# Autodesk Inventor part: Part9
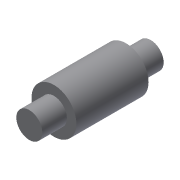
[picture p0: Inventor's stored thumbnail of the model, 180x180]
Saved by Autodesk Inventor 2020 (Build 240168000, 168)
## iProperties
Created: 2002-01
Part Number: Part9
Document SubType Name: Modeling
Designer: ***
Density: 1 g/cm^3
Material: Generic
Appearance: Default
Control State: 0
Master: False
Checked Out: False
Shininess: 77.0
Length Units: 11269
Angle Units: 11279
Time Units: 11290
Mass Units: 11283
Length Display Precision: 3
Angle Display Precision: 2
Density: 0.0
Volumn: 0.0
Area: 0.0
PropertySet Name: Model Information
Author: ***
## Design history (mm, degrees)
sketch "Sketch1"
  geometry: L1 (0.279, 23.245)-(5.19, 23.245); L2 (5.19, 23.245)-(5.19, 13.947); L3 (5.19, 13.947)-(8.761, 13.947); L4 (8.761, 13.947)-(8.761, -13.295); L5 (8.761, -13.295)-(5.19, -13.295); L6 (5.19, -13.295)-(5.19, -22.592); L7 (5.19, -22.592)-(0.279, -22.592); L8 (0.279, -22.592)-(0.279, 23.245)
  constraints: 16 end point, 5 parallel, 2 equal length, 1 collinear, 1 horizontal, 1 perpendicular
revolve "Revolution1" sketch "Sketch1" stored, may be unused: angle "d0" = 90 deg
body "Solid1"
